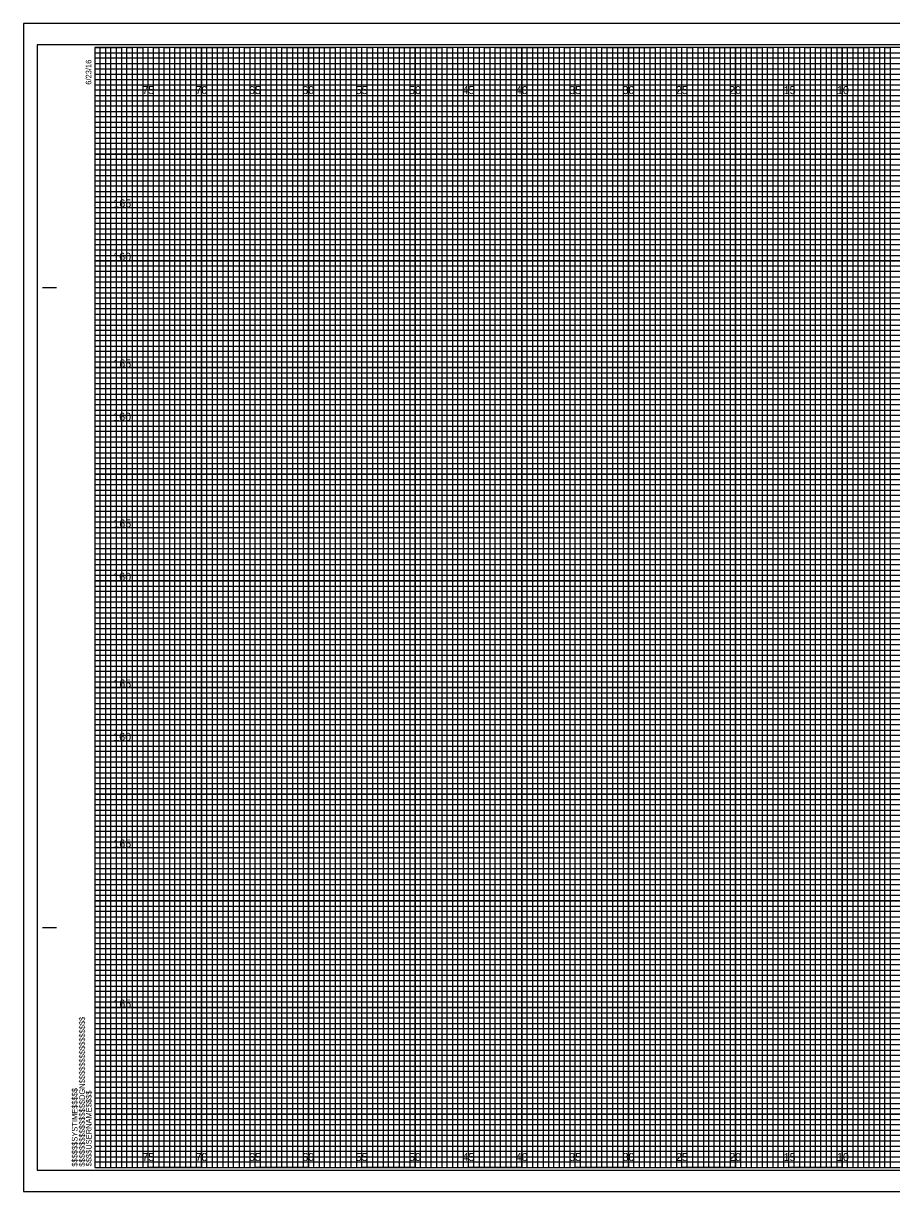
# Model space of a CAD drawing. Extents: x -7 to 162, y -2 to 107.
# Drawn here: x -6.7 to 74.6, y -2.3 to 107.3 of the extents above; entities that cross this region are included whole.
import ezdxf

# ---------------------------------------------------------------- set-up
doc = ezdxf.new("R2010")
doc.units = 0
for name, color, linetype in [('Prop CMT Conc Surface', 7, 'Continuous'), ('Prop CMT Pvmt Wedge Surface 2', 7, 'Continuous'), ('Prop XS Ditch Standard Text', 7, 'Continuous'), ('Prop XS Elevation Labels', 7, 'Continuous'), ('Prop XS Hydro Elevations', 7, 'Continuous'), ('Prop XS SE Text', 7, 'Continuous'), ('Prop XS Side Slope Text', 7, 'Continuous'), ('Sheet Cutting Line CELL', 7, 'Continuous'), ('Sheet DOT Grid CELL', 7, 'Continuous'), ('Sheet Plot Border Inside CELL', 7, 'Continuous'), ('Sheet Plot Border Outside CELL', 7, 'Continuous')]:
    doc.layers.add(name, color=color, linetype=linetype)

msp = doc.modelspace()

# ---------------------------------------------------------------- linework, layer by layer
at = {"layer": 'Prop CMT Pvmt Wedge Surface 2'}
for points in [[(0, 0), (0.5, 0), (0.5, 105), (1, 105), (1, 0)], [(1, 0), (1.5, 0), (1.5, 105), (2, 105), (2, 0)], [(2.5, 0), (3, 0), (3, 105), (3.5, 105), (3.5, 0)], [(3.5, 0), (4, 0), (4, 105), (4.5, 105), (4.5, 0)], [(5, 0), (5.5, 0), (5.5, 105), (6, 105), (6, 0)], [(6, 0), (6.5, 0), (6.5, 105), (7, 105), (7, 0)], [(7.5, 0), (8, 0), (8, 105), (8.5, 105), (8.5, 0)], [(8.5, 0), (9, 0), (9, 105), (9.5, 105), (9.5, 0)], [(10, 0), (10.5, 0), (10.5, 105), (11, 105), (11, 0)], [(11, 0), (11.5, 0), (11.5, 105), (12, 105), (12, 0)], [(12.5, 0), (13, 0), (13, 105), (13.5, 105), (13.5, 0)], [(13.5, 0), (14, 0), (14, 105), (14.5, 105), (14.5, 0)], [(15, 0), (15.5, 0), (15.5, 105), (16, 105), (16, 0)], [(16, 0), (16.5, 0), (16.5, 105), (17, 105), (17, 0)], [(17.5, 0), (18, 0), (18, 105), (18.5, 105), (18.5, 0)], [(18.5, 0), (19, 0), (19, 105), (19.5, 105), (19.5, 0)], [(20, 0), (20.5, 0), (20.5, 105), (21, 105), (21, 0)], [(21, 0), (21.5, 0), (21.5, 105), (22, 105), (22, 0)], [(22.5, 0), (23, 0), (23, 105), (23.5, 105), (23.5, 0)], [(23.5, 0), (24, 0), (24, 105), (24.5, 105), (24.5, 0)], [(25, 0), (25.5, 0), (25.5, 105), (26, 105), (26, 0)], [(26, 0), (26.5, 0), (26.5, 105), (27, 105), (27, 0)], [(27.5, 0), (28, 0), (28, 105), (28.5, 105), (28.5, 0)], [(28.5, 0), (29, 0), (29, 105), (29.5, 105), (29.5, 0)], [(30, 0), (30.5, 0), (30.5, 105), (31, 105), (31, 0)], [(31, 0), (31.5, 0), (31.5, 105), (32, 105), (32, 0)], [(32.5, 0), (33, 0), (33, 105), (33.5, 105), (33.5, 0)], [(33.5, 0), (34, 0), (34, 105), (34.5, 105), (34.5, 0)], [(35, 0), (35.5, 0), (35.5, 105), (36, 105), (36, 0)], [(36, 0), (36.5, 0), (36.5, 105), (37, 105), (37, 0)], [(37.5, 0), (38, 0), (38, 105), (38.5, 105), (38.5, 0)], [(38.5, 0), (39, 0), (39, 105), (39.5, 105), (39.5, 0)], [(40, 0), (40.5, 0), (40.5, 105), (41, 105), (41, 0)], [(41, 0), (41.5, 0), (41.5, 105), (42, 105), (42, 0)], [(42.5, 0), (43, 0), (43, 105), (43.5, 105), (43.5, 0)], [(43.5, 0), (44, 0), (44, 105), (44.5, 105), (44.5, 0)], [(45, 0), (45.5, 0), (45.5, 105), (46, 105), (46, 0)], [(46, 0), (46.5, 0), (46.5, 105), (47, 105), (47, 0)], [(47.5, 0), (48, 0), (48, 105), (48.5, 105), (48.5, 0)], [(48.5, 0), (49, 0), (49, 105), (49.5, 105), (49.5, 0)], [(50, 0), (50.5, 0), (50.5, 105), (51, 105), (51, 0)], [(51, 0), (51.5, 0), (51.5, 105), (52, 105), (52, 0)], [(52.5, 0), (53, 0), (53, 105), (53.5, 105), (53.5, 0)], [(53.5, 0), (54, 0), (54, 105), (54.5, 105), (54.5, 0)], [(55, 0), (55.5, 0), (55.5, 105), (56, 105), (56, 0)], [(56, 0), (56.5, 0), (56.5, 105), (57, 105), (57, 0)], [(57.5, 0), (58, 0), (58, 105), (58.5, 105), (58.5, 0)], [(58.5, 0), (59, 0), (59, 105), (59.5, 105), (59.5, 0)], [(60, 0), (60.5, 0), (60.5, 105), (61, 105), (61, 0)], [(61, 0), (61.5, 0), (61.5, 105), (62, 105), (62, 0)], [(62.5, 0), (63, 0), (63, 105), (63.5, 105), (63.5, 0)], [(63.5, 0), (64, 0), (64, 105), (64.5, 105), (64.5, 0)], [(65, 0), (65.5, 0), (65.5, 105), (66, 105), (66, 0)], [(66, 0), (66.5, 0), (66.5, 105), (67, 105), (67, 0)], [(67.5, 0), (68, 0), (68, 105), (68.5, 105), (68.5, 0)], [(68.5, 0), (69, 0), (69, 105), (69.5, 105), (69.5, 0)], [(70, 0), (70.5, 0), (70.5, 105), (71, 105), (71, 0)], [(71, 0), (71.5, 0), (71.5, 105), (72, 105), (72, 0)], [(72.5, 0), (73, 0), (73, 105), (73.5, 105), (73.5, 0)], [(73.5, 0), (74, 0), (74, 105), (74.5, 105), (74.5, 0)]]:
    msp.add_lwpolyline(points, dxfattribs=at)
at = {"layer": 'Prop XS Ditch Standard Text'}
for p, q in [((0, 104.5), (130, 104.5)), ((130, 103.99), (0, 103.99)), ((0, 103.99), (0, 103.5)), ((0, 103.5), (130, 103.5)), ((130, 102.95), (0, 102.95)), ((0, 102.95), (0, 102)), ((0, 102), (160, 102))]:
    msp.add_line(p, q, dxfattribs=at)
for points in [[(0, 101.5), (135, 101.5), (160, 101.5), (160, 101), (0, 101)], [(0, 100.5), (160, 100.5), (160, 99.5), (0, 99.5)], [(0, 99), (160, 99), (160, 98.5), (0, 98.49)], [(0, 98), (160, 98), (160, 97), (0, 97)], [(0, 96.5), (160, 96.5), (160, 96), (0, 96)], [(0, 95.5), (160, 95.5), (160, 94.5), (0, 94.5)], [(0, 94), (160, 94), (160, 93.5), (0, 93.5)], [(0, 93), (160, 93), (160, 92), (0, 92)], [(0, 91.5), (160, 91.5), (160, 91), (0, 91)], [(0, 90.5), (160, 90.5), (160, 89.5), (0, 89.5)], [(0, 89), (160, 89), (160, 88.5), (0, 88.5)], [(0, 88), (160, 88), (160, 86.98), (160, 86.5), (160, 86), (0, 86)], [(0, 87), (160, 87), (160, 86.5), (0, 86.5)], [(0, 85.5), (160, 85.5), (160, 84.5), (0, 84.52)], [(0, 84.52), (160, 84.5), (160, 84), (0, 84)], [(0, 83.5), (160, 83.5), (160, 83), (0, 83)], [(0, 82), (160, 82), (160, 81.5), (0, 81.5)], [(0, 81), (160, 81), (160, 80.5), (0, 80.5)], [(-0.04, 79.45), (160, 79.45), (160, 78.94), (-0.04, 78.94)], [(0, 78.5), (160, 78.5), (160, 78), (0, 78)], [(0, 77), (160, 77), (160, 76.5), (0, 76.5)], [(0, 76), (160, 76), (160, 75.5), (0, 75.5)], [(0, 74.5), (160, 74.5), (160, 74), (0, 74)], [(0, 73.5), (160, 73.5), (160, 73), (0, 73)], [(0, 72), (160, 72), (160, 71.5), (0, 71.5)], [(0, 71), (160, 71), (160, 70.5), (0, 70.5)], [(0, 69.5), (160, 69.5), (160, 68.99), (0, 69)], [(0, 68.5), (160, 68.5), (160, 68), (0, 68)], [(0, 67), (160, 67), (160, 66.5), (0, 66.5)], [(0, 66), (160, 66), (160, 65.5), (0, 65.5)], [(0, 64.5), (160, 64.5), (160, 64), (0, 64)], [(0, 63.5), (160, 63.5), (160, 63), (0, 63)], [(0, 62), (160, 62), (160, 61.5), (0, 61.5)], [(0, 61), (160, 61), (160, 60.5), (0, 60.5)], [(0, 59.5), (160, 59.5), (160, 59), (0, 59)], [(0, 58.5), (160.03, 58.45), (160, 58), (0, 58)], [(0, 57), (160, 57), (160, 56.5), (0, 56.5)], [(0, 56), (160, 56), (160, 55.5), (0, 55.5)], [(0, 54.5), (160, 54.5), (160, 54), (0, 54)], [(0, 53.5), (160, 53.5), (160, 53), (0, 53)], [(0, 52), (160, 52), (160, 51.5), (0, 51.5)], [(0, 51), (160, 51), (160, 50.5), (0, 50.5)], [(0, 49.5), (160, 49.5), (160, 49), (0, 49)], [(0, 48.5), (160, 48.5), (160, 48), (0, 48)], [(0, 47), (160, 47), (160, 46.5), (0, 46.5)], [(0, 46), (160, 46), (160, 45.5), (0, 45.5)], [(0, 44.5), (160, 44.5), (160, 44), (0, 44)], [(0, 43.5), (160, 43.5), (160, 43), (0, 43)], [(0, 42), (160, 42), (160, 41.5), (0, 41.5)], [(0, 41), (160, 41), (160, 40.5), (0, 40.5)], [(0, 39.5), (160, 39.5), (160, 38.99), (0, 39)], [(0, 38.5), (160, 38.5), (160, 38), (0, 38)], [(0, 37), (160, 37), (160, 36.5), (0, 36.5)], [(0, 36), (160, 36), (160, 35.5), (0, 35.5)], [(0, 34.5), (160, 34.5), (160, 34), (0, 34)], [(0, 33.5), (160, 33.5), (160, 33), (0, 33)], [(0, 32), (160, 32), (160, 31.5), (0, 31.5)], [(0, 31), (160, 31), (160, 30.5), (0, 30.5)], [(0, 29.5), (160, 29.5), (160, 29), (0, 29)], [(0, 28.5), (160.03, 28.46), (160, 28), (0, 28)], [(0, 27), (160, 27), (160, 26.5), (0, 26.5)], [(0, 26), (160, 26), (160, 25.5), (0, 25.5)], [(0, 24.5), (160, 24.5), (160, 24), (0, 24)], [(0, 23.5), (160, 23.5), (160, 23), (0, 23)], [(0, 22), (160, 22), (160, 21.5), (0, 21.5)], [(0, 21), (160, 21), (160, 20.5), (0, 20.5)], [(0, 19.5), (160, 19.5), (160, 19), (0, 19)], [(0, 18.5), (160, 18.5), (160, 18), (0, 18)], [(0, 17), (160, 17), (160, 16.5), (0, 16.5)], [(0, 16), (160, 16), (160, 15.5), (0, 15.5)], [(0, 14.5), (160, 14.5), (160, 14), (0, 14)], [(0, 13.5), (160, 13.5), (160, 13), (0, 13)], [(0, 12), (160, 12), (160, 11.5), (0, 11.5)], [(0, 11), (160, 11), (160, 10.5), (0, 10.5)], [(0, 9.5), (160, 9.5), (160, 9), (0, 9)], [(0, 8.5), (160, 8.5), (160, 8), (0, 8)], [(0, 7), (160, 7), (160, 6.5), (0, 6.5)], [(0, 6), (160, 6), (160, 5.5), (0, 5.5)], [(0, 4.5), (160, 4.5), (160, 4), (0, 4)], [(0, 3.5), (160, 3.5), (160, 3), (0, 3)], [(0, 2), (160, 2), (160, 1.5), (0, 1.5)], [(0, 1), (160, 1), (160, 0.5), (0, 0.5)]]:
    msp.add_lwpolyline(points, dxfattribs=at)
at = {"layer": 'Prop XS Hydro Elevations'}
for p, q in [((-4.9, 82.5), (-3.65, 82.5)), ((-4.85, 82.5), (-3.6, 82.5)), ((-4.9, 22.5), (-3.65, 22.5)), ((-4.85, 22.5), (-3.6, 22.5)), ((0, 0), (0, 0)), ((0, 0), (0, 0)), ((0, 0), (0, 0)), ((0, 0), (0, 0)), ((0, 0), (0, 0)), ((0, 0), (0, 0)), ((0, 0), (0, 0))]:
    msp.add_line(p, q, dxfattribs=at)
msp.add_lwpolyline([(160, 105), (0, 105), (0, 0), (160, 0)], close=True, dxfattribs=at)
at = {"layer": 'Prop XS SE Text'}
for points in [[(0, 105), (2.5, 105), (2.5, 0), (7.5, 0), (7.5, 105), (12.5, 105), (12.5, 0), (17.5, 0), (17.5, 105), (22.5, 105), (22.5, 0), (27.5, 0), (27.5, 105), (32.5, 105), (32.5, 0), (37.5, 0), (37.5, 105), (42.5, 105), (42.5, 0), (47.5, 0), (47.5, 105), (52.5, 105), (52.5, 0), (57.5, 0), (57.5, 105), (62.5, 105), (62.5, 0), (67.5, 0), (67.5, 105), (72.5, 105), (72.5, 0), (77.5, 0)], [(0, 102.5), (137.5, 102.5)], [(0, 92.5), (160, 92.5), (160, 97.5), (0, 97.5)], [(0, 82.5), (160, 82.5), (160, 87.5), (0, 87.5)], [(0, 72.5), (160, 72.5), (160, 77.5), (0, 77.5)], [(0, 62.5), (160, 62.5), (160, 67.5), (0, 67.5)], [(0, 52.5), (160, 52.5), (160, 57.5), (0, 57.5)], [(0, 42.5), (160, 42.5), (160, 47.5), (0, 47.5)], [(0, 32.5), (160, 32.5), (160, 37.5), (0, 37.5)], [(0, 22.5), (160, 22.5), (160, 27.5), (0, 27.5)], [(0, 12.5), (160, 12.5), (160, 17.5), (0, 17.5)], [(0, 2.5), (160, 2.5), (160, 7.5), (0, 7.5)]]:
    msp.add_lwpolyline(points, dxfattribs=at)
at = {"layer": 'Prop XS Side Slope Text'}
for p, q in [((5, 105), (0, 105)), ((5, 0), (5, 105)), ((15, 105), (10, 105)), ((10, 105), (10, 0)), ((15, 0), (15, 105)), ((25, 105), (20, 105)), ((20, 105), (20, 0)), ((25, 0), (25, 105)), ((35, 105), (30, 105)), ((30, 105), (30, 0)), ((35, 0), (35, 105)), ((45, 105), (40, 105)), ((40, 105), (40, 0)), ((45, 0), (45, 105)), ((55, 105), (50, 105)), ((50, 105), (50, 0)), ((55, 0), (55, 105)), ((65, 105), (60, 105)), ((60, 105), (60, 0)), ((65, 0), (65, 105)), ((75, 105), (70, 105)), ((70, 105), (70, 0)), ((10, 0), (5, 0)), ((20, 0), (15, 0)), ((30, 0), (25, 0)), ((40, 0), (35, 0)), ((50, 0), (45, 0)), ((60, 0), (55, 0)), ((70, 0), (65, 0))]:
    msp.add_line(p, q, dxfattribs=at)
for points in [[(0, 100), (160, 100), (160, 95), (0, 95)], [(0, 90), (160, 90), (160, 85), (0, 85)], [(0, 80), (160, 80), (160, 75), (0, 75)], [(0, 70), (160, 70), (160, 65), (0, 65)], [(0, 60), (160, 60), (160, 55), (0, 55)], [(0, 50), (160, 50), (160, 45), (0, 45)], [(0, 40), (160, 40), (160, 35), (0, 35)], [(0, 30), (160, 30), (160, 25), (0, 25)], [(0, 20), (160, 20), (160, 15), (0, 15)], [(0, 10), (160, 10), (160, 5), (0, 5)]]:
    msp.add_lwpolyline(points, dxfattribs=at)
at = {"layer": 'Sheet Cutting Line CELL'}
for p, q in [((161.65, 107.25), (-6.7, 107.25)), ((-6.7, 107.25), (-6.7, -2.25)), ((-6.7, -2.25), (161.65, -2.25))]:
    msp.add_line(p, q, dxfattribs=at)
at = {"layer": 'Sheet DOT Grid CELL'}
for p, q in [((5, 0), (5, 105)), ((10, 0), (10, 105)), ((15, 0), (15, 105)), ((20, 0), (20, 105)), ((25, 0), (25, 105)), ((30, 0), (30, 105)), ((35, 0), (35, 105)), ((40, 0), (40, 105)), ((45, 0), (45, 105)), ((50, 0), (50, 105)), ((55, 0), (55, 105)), ((60, 0), (60, 105)), ((65, 0), (65, 105)), ((70, 0), (70, 105)), ((0, 100), (160, 100)), ((0, 95), (160, 95)), ((0, 90), (160, 90)), ((0, 85), (160, 85)), ((0, 80), (160, 80)), ((0, 75), (160, 75)), ((0, 70), (160, 70)), ((0, 65), (160, 65)), ((0, 60), (160, 60)), ((0, 55), (160, 55)), ((0, 50), (160, 50)), ((0, 45), (160, 45)), ((0, 40), (160, 40)), ((0, 35), (160, 35)), ((0, 30), (160, 30)), ((0, 25), (160, 25)), ((0, 20), (160, 20)), ((0, 15), (160, 15)), ((0, 10), (160, 10)), ((0, 5), (160, 5))]:
    msp.add_line(p, q, dxfattribs=at)
at = {"layer": 'Sheet Plot Border Inside CELL'}
msp.add_lwpolyline([(-5.4, -0.25), (161.2, -0.25), (161.2, 105.25), (-5.4, 105.25)], close=True, dxfattribs=at)
at = {"layer": 'Sheet Plot Border Outside CELL'}
msp.add_lwpolyline([(-6.7, -2.25), (161.65, -2.25), (161.65, 107.25), (-6.7, 107.25)], close=True, dxfattribs=at)

# ---------------------------------------------------------------- texts
at = {"layer": 'Prop CMT Conc Surface'}
for s, p in [('75', (4.44, 100.62)), ('70', (9.43, 100.62)), ('65', (14.44, 100.62)), ('60', (19.43, 100.62)), ('55', (24.44, 100.62)), ('50', (29.43, 100.62)), ('45', (34.44, 100.62)), ('40', (39.43, 100.62)), ('35', (44.44, 100.62)), ('30', (49.43, 100.62)), ('25', (54.44, 100.62)), ('20', (59.43, 100.62)), ('15', (64.53, 100.62)), ('10', (69.52, 100.62)), ('75', (4.44, 0.62)), ('70', (9.43, 0.62)), ('65', (14.44, 0.62)), ('60', (19.43, 0.62)), ('55', (24.44, 0.62)), ('50', (29.43, 0.62)), ('45', (34.44, 0.62)), ('40', (39.43, 0.62)), ('35', (44.44, 0.62)), ('30', (49.43, 0.62)), ('25', (54.44, 0.62)), ('20', (59.43, 0.62)), ('15', (64.53, 0.62)), ('10', (69.52, 0.62))]:
    msp.add_text(s, height=0.75, dxfattribs=at).set_placement(p)
at = {"layer": 'Prop XS Elevation Labels'}
for s, p in [('165', (1.73, 90)), ('160', (1.72, 85)), ('165', (1.73, 75)), ('160', (1.72, 70)), ('165', (1.73, 60)), ('160', (1.72, 55)), ('165', (1.73, 45)), ('160', (1.72, 40)), ('165', (1.73, 30)), ('165', (1.73, 15))]:
    msp.add_text(s, height=0.75, dxfattribs=at).set_placement(p)
at = {"layer": 'Prop XS Hydro Elevations'}
for s, p in [('6/23/16', (-0.33, 101.5)), ('$$$$$$$$$$$$$$$$DGN$$$$$$$$$$$$$$$$', (-0.94, 0.09)), ('$$$$$$SYSTIME$$$$$', (-1.63, 0.09)), ('$$$$USERNAME$$$$', (-0.31, 0.12))]:
    msp.add_text(s, height=0.525, rotation=90, dxfattribs=at).set_placement(p)

doc.saveas('drawing.dxf')
